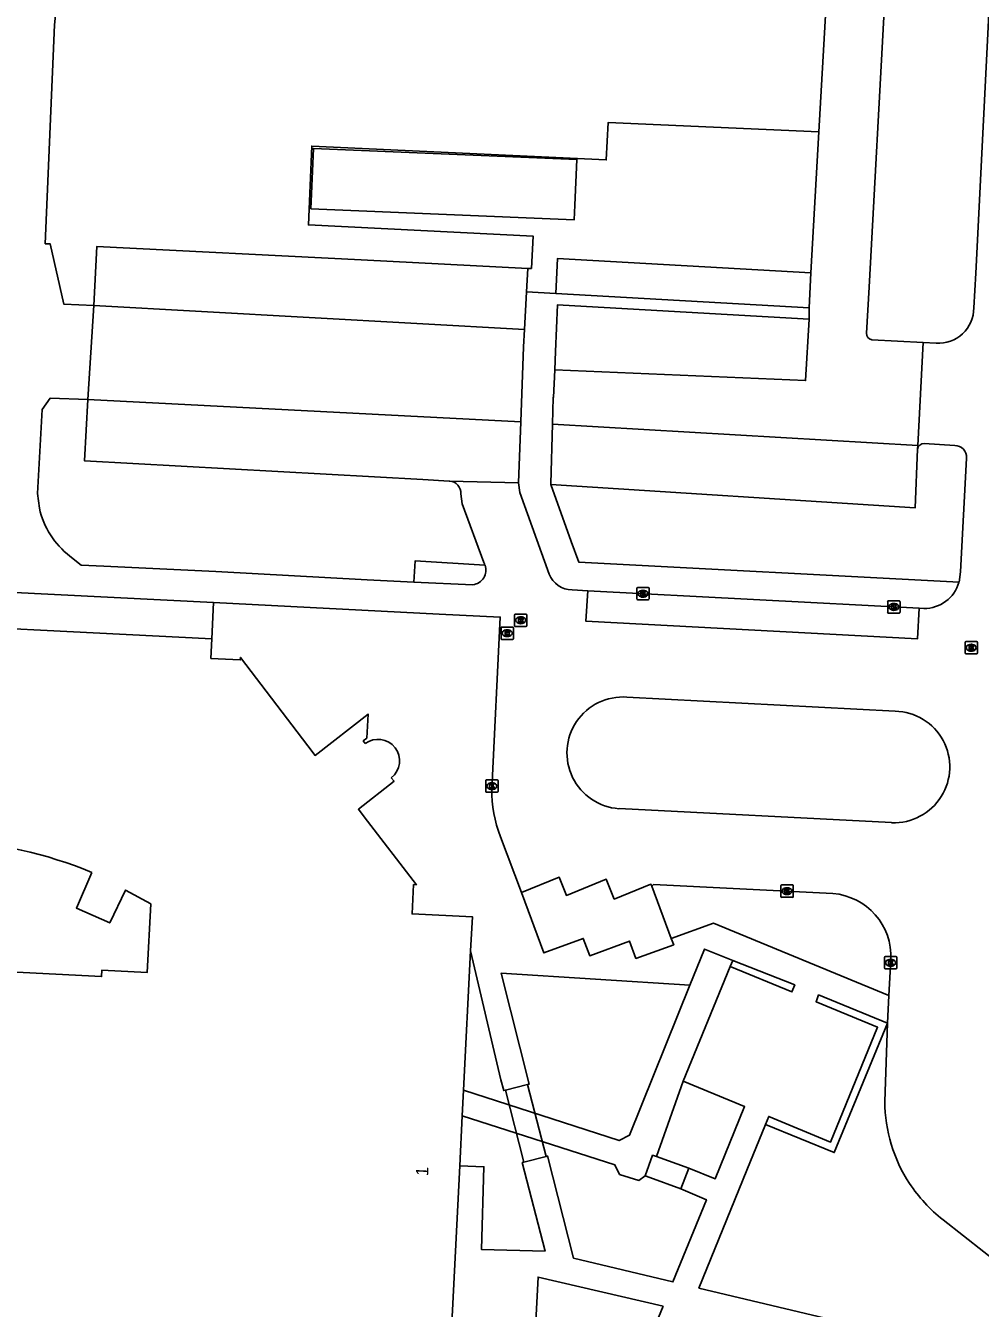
# Model space of a CAD drawing. Extents: x 161761 to 162722, y 384793 to 385405.
# Drawn here: x 161962.4 to 162039.8, y 385048.1 to 385152.1 of the extents above; entities that cross this region are included whole.
import ezdxf

# ---------------------------------------------------------------- set-up
doc = ezdxf.new("R2010")
doc.units = 0
for name, color, linetype in [('IMGEO_Berm_halfverhard', 7, 'Continuous'), ('IMGEO_Dek', 7, 'Continuous'), ('IMGEO_Kolk', 7, 'Continuous'), ('IMGEO_Muur', 7, 'Continuous'), ('IMGEO_Pand', 7, 'Continuous'), ('IMGEO_Pand_nummerreeks', 7, 'Continuous'), ('IMGEO_Parkeervlak_open', 7, 'Continuous'), ('IMGEO_Rijbaan_lokaal_open', 7, 'Continuous'), ('IMGEO_Rioolput', 7, 'Continuous'), ('IMGEO_Voetpad_op_trap', 7, 'Continuous'), ('IMGEO_Voetpad_open', 7, 'Continuous')]:
    doc.layers.add(name, color=color, linetype=linetype)

msp = doc.modelspace()

# ---------------------------------------------------------------- linework, layer by layer
at = {"layer": 'IMGEO_Berm_halfverhard'}
msp.add_lwpolyline([(162032.21, 385071.26), (162027.91, 385060.77), (162022.34, 385063.05)], dxfattribs=at)
at = {"layer": 'IMGEO_Dek'}
msp.add_lwpolyline([(162003.05, 385066.27), (162001.25, 385065.83), (162002.75, 385060), (162004.55, 385060.46)], close=True, dxfattribs=at)
at = {"layer": 'IMGEO_Kolk'}
for p, q in [((162011.9, 385105.62), (162011.9, 385106.47)), ((162011.98, 385106.55), (162012.83, 385106.55)), ((162012.39, 385106.33), (162012.41, 385106.33)), ((162012.9, 385106.47), (162012.9, 385105.62)), ((162012.83, 385105.55), (162011.98, 385105.55)), ((162012.41, 385105.77), (162012.39, 385105.77)), ((162032.24, 385104.55), (162032.24, 385105.4)), ((162032.31, 385105.48), (162033.17, 385105.48)), ((162032.73, 385105.26), (162032.75, 385105.26)), ((162033.24, 385105.4), (162033.24, 385104.55)), ((162033.17, 385104.48), (162032.31, 385104.48)), ((162032.75, 385104.7), (162032.72, 385104.7)), ((161999.65, 385090.03), (161999.65, 385090.89)), ((161999.73, 385090.96), (162000.58, 385090.96)), ((162000.14, 385090.74), (162000.16, 385090.74)), ((162000.65, 385090.89), (162000.65, 385090.03)), ((162000.58, 385089.96), (161999.73, 385089.96)), ((162000.16, 385090.18), (162000.14, 385090.18)), ((162023.58, 385081.52), (162023.58, 385082.37)), ((162023.66, 385082.45), (162024.51, 385082.45)), ((162024.07, 385082.23), (162024.1, 385082.23)), ((162024.58, 385082.37), (162024.58, 385081.52)), ((162024.51, 385081.45), (162023.66, 385081.45)), ((162024.09, 385081.67), (162024.07, 385081.67)), ((162031.98, 385075.73), (162031.98, 385076.58)), ((162032.05, 385076.65), (162032.9, 385076.65)), ((162032.46, 385076.43), (162032.49, 385076.43)), ((162032.98, 385076.58), (162032.98, 385075.73)), ((162032.9, 385075.65), (162032.05, 385075.65)), ((162032.49, 385075.87), (162032.46, 385075.87))]:
    msp.add_line(p, q, dxfattribs=at)
for points in [[(162011.9, 385105.62), (162011.9, 385106.47)], [(162011.98, 385106.55), (162012.83, 385106.55)], [(162012.22, 385106.25), (162012.35, 385106.25), (162012.35, 385106.1), (162012.47, 385106.25), (162012.64, 385106.25), (162012.49, 385106.1), (162012.65, 385105.85), (162012.49, 385105.85), (162012.41, 385106.01), (162012.35, 385105.94), (162012.35, 385105.85), (162012.22, 385105.85), (162012.22, 385106.25)], [(162012.9, 385106.47), (162012.9, 385105.62)], [(162012.83, 385105.55), (162011.98, 385105.55)], [(162032.24, 385104.55), (162032.24, 385105.4)], [(162032.31, 385105.48), (162033.17, 385105.48)], [(162032.56, 385105.18), (162032.68, 385105.18), (162032.68, 385105.03), (162032.81, 385105.18), (162032.98, 385105.18), (162032.83, 385105.03), (162032.98, 385104.78), (162032.83, 385104.78), (162032.75, 385104.94), (162032.68, 385104.87), (162032.68, 385104.78), (162032.56, 385104.78), (162032.56, 385105.18)], [(162033.24, 385105.4), (162033.24, 385104.55)], [(162033.17, 385104.48), (162032.31, 385104.48)], [(161999.65, 385090.03), (161999.65, 385090.89)], [(161999.73, 385090.96), (162000.58, 385090.96)], [(161999.97, 385090.66), (162000.1, 385090.66), (162000.1, 385090.51), (162000.22, 385090.66), (162000.39, 385090.66), (162000.24, 385090.51), (162000.4, 385090.26), (162000.24, 385090.26), (162000.16, 385090.42), (162000.1, 385090.36), (162000.1, 385090.26), (161999.97, 385090.26), (161999.97, 385090.66)], [(162000.65, 385090.89), (162000.65, 385090.03)], [(162000.58, 385089.96), (161999.73, 385089.96)], [(162023.58, 385081.52), (162023.58, 385082.37)], [(162023.66, 385082.45), (162024.51, 385082.45)], [(162024.58, 385082.37), (162024.58, 385081.52)], [(162024.51, 385081.45), (162023.66, 385081.45)], [(162023.9, 385082.15), (162024.03, 385082.15), (162024.03, 385081.99), (162024.16, 385082.15), (162024.32, 385082.15), (162024.18, 385082), (162024.33, 385081.75), (162024.18, 385081.75), (162024.09, 385081.91), (162024.03, 385081.84), (162024.03, 385081.75), (162023.9, 385081.75), (162023.9, 385082.15)], [(162031.98, 385075.73), (162031.98, 385076.58)], [(162032.05, 385076.65), (162032.9, 385076.65)], [(162032.3, 385076.35), (162032.42, 385076.35), (162032.42, 385076.2), (162032.55, 385076.35), (162032.71, 385076.35), (162032.57, 385076.2), (162032.72, 385075.95), (162032.57, 385075.95), (162032.48, 385076.12), (162032.42, 385076.05), (162032.42, 385075.95), (162032.3, 385075.95), (162032.3, 385076.35)], [(162032.98, 385076.58), (162032.98, 385075.73)], [(162032.9, 385075.65), (162032.05, 385075.65)]]:
    msp.add_lwpolyline(points, dxfattribs=at)
for centre, start, end in [((162011.98, 385106.47), 91.552, 178.448), ((162011.98, 385106.47), 91.552, 178.448), ((162012.83, 385106.47), 1.552, 88.448), ((162012.83, 385106.47), 1.552, 88.448), ((162011.98, 385105.62), 181.552, 268.448), ((162011.98, 385105.62), 181.552, 268.448), ((162012.83, 385105.62), 271.552, 358.448), ((162012.83, 385105.62), 271.552, 358.448), ((162032.31, 385105.4), 91.552, 178.448), ((162032.31, 385105.4), 91.552, 178.448), ((162033.16, 385105.4), 1.552, 88.448), ((162033.16, 385105.4), 1.552, 88.448), ((162032.31, 385104.55), 181.552, 268.448), ((162032.31, 385104.55), 181.552, 268.448), ((162033.16, 385104.55), 271.552, 358.448), ((162033.16, 385104.55), 271.552, 358.448), ((161999.73, 385090.88), 91.552, 178.448), ((161999.73, 385090.88), 91.552, 178.448), ((162000.58, 385090.88), 1.552, 88.448), ((162000.58, 385090.88), 1.552, 88.448), ((161999.73, 385090.04), 181.552, 268.448), ((161999.73, 385090.04), 181.552, 268.448), ((162000.58, 385090.04), 271.552, 358.448), ((162000.58, 385090.04), 271.552, 358.448), ((162023.66, 385082.37), 91.552, 178.448), ((162023.66, 385082.37), 91.552, 178.448), ((162024.51, 385082.37), 1.552, 88.448), ((162024.51, 385082.37), 1.552, 88.448), ((162023.66, 385081.52), 181.552, 268.448), ((162023.66, 385081.52), 181.552, 268.448), ((162024.51, 385081.52), 271.552, 358.448), ((162024.51, 385081.52), 271.552, 358.448), ((162032.05, 385076.58), 91.552, 178.448), ((162032.05, 385076.58), 91.552, 178.448), ((162032.9, 385076.58), 1.552, 88.448), ((162032.9, 385076.58), 1.552, 88.448), ((162032.05, 385075.73), 181.552, 268.448), ((162032.05, 385075.73), 181.552, 268.448), ((162032.9, 385075.73), 271.552, 358.448), ((162032.9, 385075.73), 271.552, 358.448)]:
    msp.add_arc(centre, 0.0765, start, end, dxfattribs=at)
for centre, major_axis, ratio, start_param, end_param in [((162012.39, 385106.05), (-0.387, 0.002), 0.722429, 4.712389, 7.853982), ((162012.41, 385106.05), (-0.39, 0.002), 0.717154, 1.570796, 4.712389), ((162032.73, 385104.98), (-0.387, 0.002), 0.722429, 4.712389, 7.853982), ((162032.75, 385104.98), (-0.39, 0.002), 0.717154, 1.570796, 4.712389), ((162000.14, 385090.46), (-0.387, 0.002), 0.722429, 4.712389, 7.853982), ((162000.16, 385090.46), (-0.39, 0.002), 0.717154, 1.570796, 4.712389), ((162024.07, 385081.95), (-0.387, 0.002), 0.722429, 4.712389, 7.853982), ((162024.09, 385081.95), (-0.39, 0.002), 0.717154, 1.570796, 4.712389), ((162032.46, 385076.15), (-0.387, 0.002), 0.722429, 4.712389, 7.853982), ((162032.49, 385076.15), (-0.39, 0.002), 0.717154, 1.570796, 4.712389)]:
    msp.add_ellipse(centre, major_axis=major_axis, ratio=ratio, start_param=start_param, end_param=end_param, dxfattribs=at)
at = {"layer": 'IMGEO_Muur'}
for points in [[(162017.38, 385077.25), (162016.19, 385074.33)], [(162019.48, 385075.85), (162019.68, 385076.34)], [(162015.67, 385066.54), (162019.48, 385075.85)]]:
    msp.add_lwpolyline(points, dxfattribs=at)
at = {"layer": 'IMGEO_Pand'}
for points in [[(161985.48, 385137.24), (161985.69, 385142.13), (162007.03, 385141.23), (162006.87, 385137.52), (162006.82, 385136.34), (161985.48, 385137.24)], [(161977.45, 385102.4), (161917.59, 385105.41), (161916.87, 385091)], [(161989.89, 385093.9), (161989.72, 385094.12), (161990.03, 385094.35), (161990.12, 385096.3), (161985.82, 385092.94), (161985.24, 385093.71), (161979.77, 385100.88), (161979.76, 385100.69), (161977.38, 385100.81), (161977.45, 385102.4)], [(161998.43, 385077.1), (161998.57, 385079.87), (161993.69, 385080.11), (161993.81, 385082.48), (161994.03, 385082.47), (161989.8, 385087.97), (161989.33, 385088.58), (161992.22, 385090.86), (161992, 385091.14)], [(161944.24, 385084.57), (161945.13, 385081.64), (161942.46, 385080.71), (161941.34, 385083.49), (161939.31, 385082.54), (161939.07, 385076.98), (161945.75, 385076.68), (161945.74, 385076.2), (161968.52, 385075.03), (161968.53, 385075.54), (161972.21, 385075.37), (161972.51, 385080.92), (161970.46, 385082.04), (161969.17, 385079.37), (161966.48, 385080.57), (161967.73, 385083.47)], [(161997.86, 385065.81), (161998.43, 385077.1)], [(161997.75, 385063.75), (161997.86, 385065.81)], [(161997.55, 385059.68), (161997.75, 385063.75)], [(162006, 385026.3), (162000, 385026.62), (161995.87, 385026.83), (161995.97, 385028.69), (162000, 385029.49), (162003.68, 385030.21), (162003.97, 385034.86), (162001.08, 385034.7), (162000, 385035.59), (161997.28, 385037.85), (161996.44, 385037.9), (161997.55, 385059.68)]]:
    msp.add_lwpolyline(points, dxfattribs=at)
for centre, radius, start, end in [((161990.93, 385092.51), 1.74, 308.0027, 127.0159), ((161954.46, 385051.32), 34.78, 67.5709, 107.0866)]:
    msp.add_arc(centre, radius, start, end, dxfattribs=at)
at = {"layer": 'IMGEO_Parkeervlak_open'}
for points in [[(162003.08, 385132.41), (161989.57, 385133.1), (161968.14, 385134.19), (161967.88, 385129.39)], [(161996.73, 385115.18), (161996.68, 385115.18), (161994.55, 385115.29), (161967.14, 385116.81), (161967.41, 385121.79)], [(162034.66, 385117.75), (162034.47, 385113.01), (162004.94, 385114.91)], [(162014.69, 385078.1), (162013.11, 385082.34)]]:
    msp.add_lwpolyline(points, dxfattribs=at)
at = {"layer": 'IMGEO_Rijbaan_lokaal_open'}
for points in [[(162027.69, 385162.43), (162027.32, 385155.33), (162027.23, 385153.37), (162026.66, 385143.46)], [(162030.52, 385127.16), (162030.75, 385130.88), (162032.02, 385154.29)], [(162026.66, 385143.46), (162026.02, 385132.06)], [(162026.02, 385132.06), (162025.86, 385129.2)], [(161967.41, 385121.79), (161967.88, 385129.39)], [(162002.8, 385127.45), (161967.88, 385129.39)], [(162025.86, 385129.2), (162025.87, 385128.28)], [(162025.87, 385128.28), (162025.58, 385123.32), (162005.25, 385124.19)], [(162002.49, 385119.97), (162002.72, 385126.05), (162002.8, 385127.45)], [(162035.12, 385126.4), (162030.95, 385126.62)], [(162035.12, 385126.4), (162034.68, 385118.05)], [(162005.25, 385124.19), (162005.15, 385121.95), (162005.12, 385121.95), (162005.06, 385119.79)], [(161967.41, 385121.79), (162002.49, 385119.97)], [(162005.06, 385119.79), (162034.68, 385118.05)]]:
    msp.add_lwpolyline(points, dxfattribs=at)
msp.add_arc((162031.04, 385127.13), 0.516, 176.6761, 260.6176, dxfattribs=at)
at = {"layer": 'IMGEO_Rioolput'}
for p, q in [((162001.99, 385103.47), (162001.99, 385104.33)), ((162002.06, 385104.4), (162002.92, 385104.4)), ((162002.48, 385104.18), (162002.5, 385104.18)), ((162002.99, 385104.33), (162002.99, 385103.47)), ((162000.9, 385102.42), (162000.9, 385103.27)), ((162000.97, 385103.35), (162001.82, 385103.35)), ((162001.39, 385103.13), (162001.41, 385103.13)), ((162001.9, 385103.27), (162001.9, 385102.42)), ((162002.92, 385103.4), (162002.06, 385103.4)), ((162002.5, 385103.62), (162002.47, 385103.62)), ((162001.82, 385102.35), (162000.97, 385102.35)), ((162001.41, 385102.57), (162001.38, 385102.57)), ((162038.51, 385101.25), (162038.51, 385102.1)), ((162038.59, 385102.17), (162039.44, 385102.17)), ((162039, 385101.95), (162039.02, 385101.95)), ((162039.51, 385102.1), (162039.51, 385101.25)), ((162039.44, 385101.17), (162038.59, 385101.17)), ((162039.02, 385101.39), (162039, 385101.39))]:
    msp.add_line(p, q, dxfattribs=at)
for points in [[(162001.99, 385103.47), (162001.99, 385104.33)], [(162002.06, 385104.4), (162002.92, 385104.4)], [(162002.58, 385104.1), (162002.32, 385104.1), (162002.32, 385103.7)], [(162002.5, 385104.02), (162002.45, 385104.02), (162002.45, 385103.94)], [(162002.99, 385104.33), (162002.99, 385103.47)], [(162000.9, 385102.42), (162000.9, 385103.27)], [(162000.97, 385103.35), (162001.82, 385103.35)], [(162001.49, 385103.05), (162001.23, 385103.05), (162001.23, 385102.65)], [(162001.41, 385102.97), (162001.36, 385102.97), (162001.36, 385102.89)], [(162001.9, 385103.27), (162001.9, 385102.42)], [(162002.92, 385103.4), (162002.06, 385103.4)], [(162002.32, 385103.7), (162002.45, 385103.7), (162002.45, 385103.86), (162002.46, 385103.86)], [(162002.45, 385103.94), (162002.5, 385103.94)], [(162002.51, 385103.83), (162002.58, 385103.7), (162002.72, 385103.7), (162002.65, 385103.83)], [(162001.82, 385102.35), (162000.97, 385102.35)], [(162001.23, 385102.65), (162001.36, 385102.65), (162001.36, 385102.81), (162001.37, 385102.81)], [(162001.36, 385102.89), (162001.41, 385102.89)], [(162001.42, 385102.78), (162001.49, 385102.65), (162001.63, 385102.65), (162001.56, 385102.77)], [(162038.51, 385101.25), (162038.51, 385102.1)], [(162038.59, 385102.17), (162039.44, 385102.17)], [(162039.51, 385102.1), (162039.51, 385101.25)], [(162039.44, 385101.17), (162038.59, 385101.17)], [(162039.1, 385101.87), (162038.85, 385101.87), (162038.85, 385101.47)], [(162038.85, 385101.47), (162038.97, 385101.47), (162038.97, 385101.64), (162038.98, 385101.64)], [(162039.03, 385101.79), (162038.97, 385101.79), (162038.97, 385101.71)], [(162038.97, 385101.71), (162039.02, 385101.71)], [(162039.03, 385101.61), (162039.1, 385101.47), (162039.24, 385101.47), (162039.18, 385101.6)]]:
    msp.add_lwpolyline(points, dxfattribs=at)
for centre, radius, start, end in [((162002.06, 385104.32), 0.0765, 91.552, 178.448), ((162002.06, 385104.32), 0.0765, 91.552, 178.448), ((162002.51, 385103.92), 0.0964, 77.0061, 93.1865), ((162002.52, 385103.98), 0.0378, 276.6634, 79.6772), ((162002.58, 385103.99), 0.109, 350.3612, 89.416), ((162002.91, 385104.32), 0.0765, 1.552, 88.448), ((162002.91, 385104.32), 0.0765, 1.552, 88.448), ((162000.97, 385103.27), 0.0765, 91.552, 178.448), ((162000.97, 385103.27), 0.0765, 91.552, 178.448), ((162001.42, 385102.87), 0.0964, 77.0061, 93.1865), ((162001.43, 385102.93), 0.0378, 276.6634, 79.6772), ((162001.49, 385102.94), 0.109, 350.3612, 89.416), ((162001.82, 385103.27), 0.0765, 1.552, 88.448), ((162001.82, 385103.27), 0.0765, 1.552, 88.448), ((162002.06, 385103.47), 0.0765, 181.552, 268.448), ((162002.06, 385103.47), 0.0765, 181.552, 268.448), ((162002.46, 385103.81), 0.0533, 26.0293, 88.6989), ((162002.49, 385104.13), 0.19, 274.7715, 282.9687), ((162002.57, 385103.99), 0.112, 277.5842, 350.9817), ((162002.56, 385103.77), 0.108, 29.5134, 73.7905), ((162002.91, 385103.47), 0.0765, 271.552, 358.448), ((162002.91, 385103.47), 0.0765, 271.552, 358.448), ((162000.97, 385102.42), 0.0765, 181.552, 268.448), ((162000.97, 385102.42), 0.0765, 181.552, 268.448), ((162001.37, 385102.76), 0.0533, 26.0293, 88.6989), ((162001.39, 385103.08), 0.19, 274.7715, 282.9687), ((162001.48, 385102.94), 0.112, 277.5842, 350.9817), ((162001.47, 385102.72), 0.108, 29.5134, 73.7905), ((162001.82, 385102.42), 0.0765, 271.552, 358.448), ((162001.82, 385102.42), 0.0765, 271.552, 358.448), ((162038.59, 385102.1), 0.0765, 91.552, 178.448), ((162038.59, 385102.1), 0.0765, 91.552, 178.448), ((162039.44, 385102.1), 0.0765, 1.552, 88.448), ((162039.44, 385102.1), 0.0765, 1.552, 88.448), ((162038.59, 385101.25), 0.0765, 181.552, 268.448), ((162038.59, 385101.25), 0.0765, 181.552, 268.448), ((162038.98, 385101.58), 0.0533, 26.0293, 88.6989), ((162039.01, 385101.9), 0.19, 274.7715, 282.9687), ((162039.03, 385101.7), 0.0964, 77.0061, 93.1865), ((162039.05, 385101.75), 0.0378, 276.6634, 79.6772), ((162039.1, 385101.76), 0.109, 350.3612, 89.416), ((162039.1, 385101.76), 0.112, 277.5842, 350.9817), ((162039.08, 385101.55), 0.108, 29.5134, 73.7905), ((162039.44, 385101.25), 0.0765, 271.552, 358.448), ((162039.44, 385101.25), 0.0765, 271.552, 358.448)]:
    msp.add_arc(centre, radius, start, end, dxfattribs=at)
for centre, major_axis, ratio, start_param, end_param in [((162002.48, 385103.9), (-0.387, 0.002), 0.722429, 4.712389, 7.853982), ((162002.5, 385103.9), (-0.39, 0.002), 0.717154, 1.570796, 4.712389), ((162001.38, 385102.85), (-0.387, 0.002), 0.722429, 4.712389, 7.853982), ((162001.41, 385102.85), (-0.39, 0.002), 0.717154, 1.570796, 4.712389), ((162039, 385101.67), (-0.387, 0.002), 0.722429, 4.712389, 7.853982), ((162039.02, 385101.67), (-0.39, 0.002), 0.717154, 1.570796, 4.712389)]:
    msp.add_ellipse(centre, major_axis=major_axis, ratio=ratio, start_param=start_param, end_param=end_param, dxfattribs=at)
at = {"layer": 'IMGEO_Voetpad_op_trap'}
for points in [[(162013.49, 385060.44), (162016.12, 385059.51)], [(162015.47, 385057.82), (162012.97, 385058.74), (162012.59, 385058.88)]]:
    msp.add_lwpolyline(points, dxfattribs=at)
at = {"layer": 'IMGEO_Voetpad_open'}
for points in [[(162043.14, 385206.97), (162039.38, 385132.01), (162039.22, 385129.2)], [(161967.88, 385129.39), (161965.45, 385129.52), (161964.36, 385134.39), (161963.95, 385134.41), (161964.69, 385152.15), (161965.16, 385156.64)], [(162026.66, 385143.46), (162009.57, 385144.22), (162009.42, 385141.2), (161985.55, 385142.31), (161985.28, 385135.93), (162003.49, 385135.03), (162003.36, 385132.4), (162003.08, 385132.41)], [(162005.34, 385130.37), (162005.48, 385133.21), (162026.02, 385132.06)], [(162003.08, 385132.41), (162002.97, 385130.51)], [(162002.8, 385127.45), (162002.97, 385130.51)], [(162002.97, 385130.51), (162005.34, 385130.37)], [(162005.34, 385130.37), (162025.86, 385129.2)], [(162025.87, 385128.28), (162005.93, 385129.44), (162005.47, 385129.45), (162005.31, 385125.67), (162005.25, 385124.19)], [(162036.16, 385126.34), (162035.12, 385126.4)], [(161963.48, 385112.97), (161963.32, 385114.17), (161963.7, 385120.97), (161964.34, 385121.88), (161967.41, 385121.79)], [(162002.49, 385119.97), (162002.3, 385115.02)], [(162005.06, 385119.79), (162004.92, 385114.98), (162004.94, 385114.91)], [(162034.68, 385118.05), (162034.66, 385117.75)], [(162035.19, 385118.22), (162037.68, 385118.06)], [(162038.62, 385117.04), (162038.13, 385107.82), (162038.02, 385106.97)], [(162002.3, 385115.02), (161996.73, 385115.18)], [(162004.8, 385107.64), (162002.43, 385114.24), (162002.3, 385115.02)], [(162004.94, 385114.91), (162006.58, 385110.27), (162007.19, 385108.61), (162038.02, 385106.97)], [(161997.64, 385114.14), (161997.75, 385113.34), (161999.5, 385108.57)], [(161906.14, 385108.94), (161977.6, 385105.33)], [(161993.83, 385106.99), (161990.05, 385107.16), (161977.77, 385107.84), (161968.71, 385108.28), (161966.86, 385108.37), (161965.95, 385109.1)], [(161993.83, 385106.99), (161993.93, 385108.7), (161999.59, 385108.36)], [(161998.61, 385106.78), (161993.83, 385106.99)], [(162007.92, 385106.28), (162006.65, 385106.35)], [(162034.78, 385104.87), (162034.65, 385102.38), (162007.78, 385103.81), (162007.92, 385106.28)], [(162007.92, 385106.28), (162034.78, 385104.87)], [(161977.45, 385102.4), (161977.6, 385105.33)], [(161977.6, 385105.33), (161995.88, 385104.4), (162000.83, 385104.15), (162000.14, 385090.22)], [(162035.18, 385104.85), (162034.78, 385104.87)], [(162011.1, 385097.67), (162032.85, 385096.53)], [(162032.56, 385087.5), (162010.46, 385088.64)], [(162000.86, 385086.36), (162002.55, 385081.83)], [(162002.55, 385081.83), (162005.61, 385083.07), (162006.2, 385081.6), (162009.43, 385082.91), (162010.07, 385081.31), (162013.04, 385082.51), (162013.11, 385082.34)], [(162013.11, 385082.34), (162013.26, 385082.5), (162027.79, 385081.76)], [(162002.55, 385081.83), (162004.37, 385076.95), (162007.56, 385078.12), (162008.09, 385076.71), (162011.3, 385077.9), (162011.83, 385076.5), (162014.89, 385077.61), (162014.69, 385078.1)], [(162014.69, 385078.1), (162018.11, 385079.36), (162032.34, 385073.48)], [(162016.19, 385074.33), (162000.9, 385075.3), (162003.17, 385066.3), (162003.05, 385066.27), (162001.25, 385065.83), (162001.12, 385065.79), (162000.88, 385066.65), (161998.43, 385077.1)], [(162019.68, 385076.34), (162017.38, 385077.25), (162016.19, 385074.33)], [(162019.68, 385076.34), (162024.71, 385074.35), (162024.47, 385073.79), (162019.48, 385075.85)], [(162019.48, 385075.85), (162019.68, 385076.34)], [(162032.49, 385076.39), (162032.34, 385073.48)], [(162015.67, 385066.54), (162019.48, 385075.85)], [(162016.19, 385074.33), (162011.32, 385062.17), (162010.46, 385061.74), (161997.86, 385065.81)], [(162032.21, 385071.26), (162026.64, 385073.54), (162026.43, 385072.98), (162031.42, 385070.92), (162027.61, 385061.62), (162022.6, 385063.69), (162022.34, 385063.05)], [(162032.34, 385073.48), (162032.23, 385071.26)], [(162032.23, 385071.26), (162032, 385064.91)], [(162032.23, 385071.26), (162032.21, 385071.26)], [(162003.05, 385066.27), (162001.25, 385065.83), (162002.75, 385060), (162004.55, 385060.46), (162003.05, 385066.27)], [(162013.49, 385060.44), (162015.67, 385066.54)], [(162016.12, 385059.51), (162018.25, 385058.63), (162020.64, 385064.49), (162015.67, 385066.54)], [(161997.75, 385063.75), (162010.13, 385059.76), (162010.51, 385059), (162012.07, 385058.51), (162012.57, 385058.88), (162012.59, 385058.88)], [(162022.34, 385063.05), (162020.82, 385059.33), (162016.93, 385049.79), (162056.76, 385040.34), (162056.82, 385040.58)], [(161997.55, 385059.68), (161999.51, 385059.62), (161999.32, 385052.9), (162004.46, 385052.78), (162002.61, 385059.96), (162002.75, 385060), (162004.55, 385060.46), (162004.66, 385060.49), (162006.78, 385052.2), (162014.83, 385050.29), (162017.54, 385056.94), (162015.47, 385057.82)], [(162012.59, 385058.88), (162013.18, 385060.55), (162013.49, 385060.44)], [(162016.12, 385059.51), (162015.47, 385057.82)], [(162036.73, 385055.32), (162043.34, 385050.14), (162051.71, 385043.57)], [(162014.04, 385048.31), (162007.28, 385031.89), (162005.7, 385032), (162005.97, 385036.72), (162003.17, 385036.87), (162003.9, 385050.68), (162014.04, 385048.31)]]:
    msp.add_lwpolyline(points, dxfattribs=at)
for centre, radius, start, end in [((162036.36, 385129.2), 2.86, 266.16, 0.0211), ((162035.17, 385117.71), 0.503, 87.101, 175.7463), ((162037.67, 385117.11), 0.953, 356.0779, 89.2379), ((161996.66, 385114.2), 0.981, 356.3014, 85.6404), ((161970, 385114.41), 6.68, 192.4566, 232.6372), ((161998.48, 385107.96), 1.19, 276.3726, 19.6623), ((161998.56, 385108.01), 1.09, 19.0383, 30.9032), ((162006.69, 385108.38), 2.03, 201.5208, 268.8157), ((162035.2, 385107.78), 2.93, 269.6234, 343.8833), ((162010.77, 385093.15), 4.53, 85.8757, 266.0406), ((162032.75, 385092.01), 4.52, 267.5846, 88.7091), ((162009.87, 385090.03), 9.73, 178.8831, 202.1753), ((162027.4, 385076.67), 5.1, 356.7622, 85.6837), ((162044.23, 385064.98), 12.23, 180.3504, 213.3233), ((162044.2, 385064.97), 12.2, 213.3248, 232.225)]:
    msp.add_arc(centre, radius, start, end, dxfattribs=at)

# ---------------------------------------------------------------- texts
at = {"layer": 'IMGEO_Pand_nummerreeks'}
msp.add_text('1', height=1, rotation=87.0896, dxfattribs=at).set_placement((161994.98, 385058.85))

doc.saveas('drawing.dxf')
